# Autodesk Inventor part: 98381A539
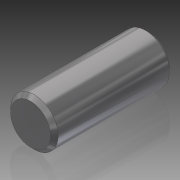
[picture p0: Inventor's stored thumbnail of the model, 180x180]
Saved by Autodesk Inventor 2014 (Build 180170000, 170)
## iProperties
Created: 2015-04
Part Number: 98381A539
Material: Stainless Steel
Document SubType Name: Modeling
Designer: Brad Factor
Density: 8.08 g/cm^3
Appearance: Semi-Polished
Author: Brad Factor
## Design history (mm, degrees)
sketch "Sketch1"
  geometry: C1 r 3.175 at (0, 0); 1 further point
  constraints: 1 centre point, 1 coincident
  dimensions: "d0" = 6.35 diameter of C1
extrude "Extrusion1" new body sketch "Sketch1" stored distance "d1" = 15.875; taper "d2" = 0 deg
chamfer "Chamfer1" distance "d3" = 0.508; stored, may be unused: second distance "d4" = 3.175, angle "d5" = 45 deg
body "Solid1"
